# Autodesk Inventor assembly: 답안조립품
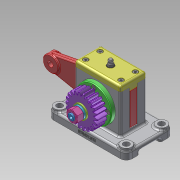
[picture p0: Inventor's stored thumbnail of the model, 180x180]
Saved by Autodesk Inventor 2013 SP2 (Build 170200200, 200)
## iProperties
Created: 2025-04
Part Number: 답안조립품
Document SubType Name: Assembly
Designer: i
Author: i
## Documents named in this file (15)
- C:\Users\i\Desktop\750404V1005\답안조립품.iam
- C:\Users\i\Desktop\750404V1005\본체.ipt
- C:\Users\i\Desktop\750404V1005\그리스 니플 M6x0.75.ipt
- C:\Users\i\Desktop\750404V1005\로드.ipt
- C:\Users\i\Desktop\750404V1005\스퍼기어.ipt
- C:\Users\i\Desktop\750404V1005\스프링와셔 M10.ipt
- C:\Users\i\Desktop\750404V1005\실링.ipt
- C:\Users\i\Desktop\750404V1005\앞커버.ipt
- C:\Users\i\Desktop\750404V1005\윗커버.ipt
- C:\Users\i\Desktop\750404V1005\육각 너트 M10.ipt
- C:\Users\i\Desktop\750404V1005\육각 소켓 머리 볼트 M4x10.ipt
- C:\Users\i\Desktop\750404V1005\편심축.ipt
- C:\Users\i\Desktop\750404V1005\평와셔 M10.ipt
- C:\Users\i\Desktop\750404V1005\평행키 4x4x10.ipt
- C:\Users\i\Desktop\750404V1005\플랜지 오일레스 부시.ipt
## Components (3 placed, 2 different names)
1. 그리스 니플 M6x0.75:1
2. 플랜지 오일레스 부시:1
3. 플랜지 오일레스 부시:2
